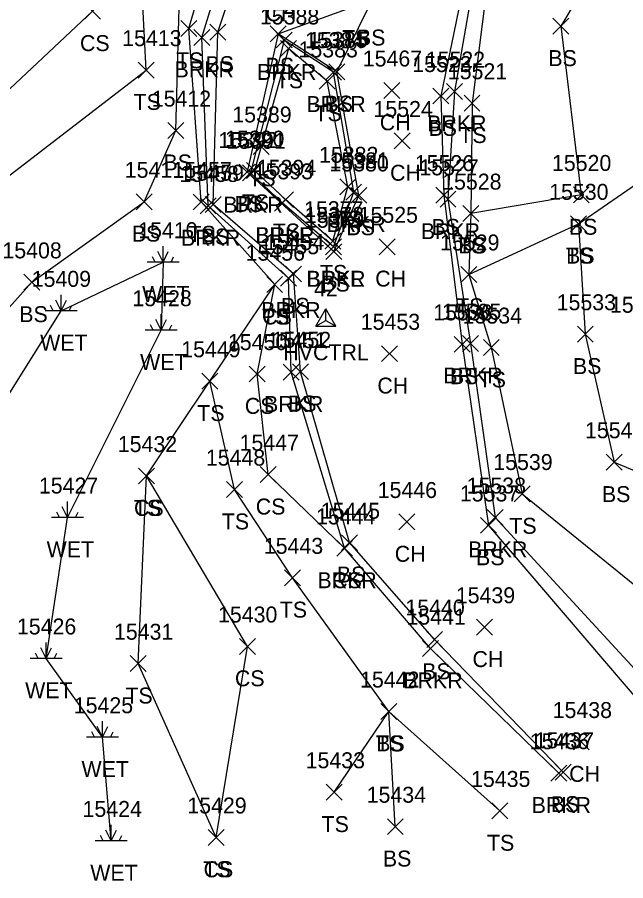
# Model space of a CAD drawing. Extents: x 1606530 to 1613020, y 784959 to 789666.
# Drawn here: x 1609105.8 to 1609182, y 788227.2 to 788335.5 of the extents above; entities that cross this region are included whole.
import ezdxf

# ---------------------------------------------------------------- set-up
doc = ezdxf.new("R2010")
doc.units = 0
for name, color, linetype in [('C_A', 7, 'Continuous'), ('C_I', 7, 'Continuous'), ('CPSM', 7, 'Continuous'), ('L_A', 7, 'Continuous'), ('L_I', 7, 'Continuous'), ('L_TIC', 7, 'Continuous'), ('LAWE', 7, 'Continuous'), ('LELB', 7, 'Continuous'), ('LWET', 7, 'Continuous')]:
    doc.layers.add(name, color=color, linetype=linetype)

msp = doc.modelspace()

# ---------------------------------------------------------------- linework, layer by layer
at = {"layer": 'CPSM'}
for p, q in [((1609143.18, 788296.73), (1609144.43, 788298.9)), ((1609145.68, 788296.73), (1609144.43, 788298.9)), ((1609144.43, 788297.45), (1609144.43, 788298.9)), ((1609143.18, 788296.73), (1609144.43, 788297.45)), ((1609144.43, 788297.45), (1609144.43, 788297.45)), ((1609144.43, 788297.45), (1609145.68, 788296.73)), ((1609143.18, 788296.73), (1609145.68, 788296.73))]:
    msp.add_line(p, q, dxfattribs=at)
at = {"layer": 'L_TIC'}
for points in [[(1609114.19, 788335.22), (1609116.19, 788337.22)], [(1609116.19, 788335.22), (1609114.19, 788337.22)], [(1609126.26, 788333.06), (1609128.26, 788335.06)], [(1609128.26, 788333.06), (1609126.26, 788335.06)], [(1609172.89, 788333.34), (1609174.89, 788335.34)], [(1609174.89, 788333.34), (1609172.89, 788335.34)], [(1609127.89, 788331.92), (1609129.89, 788333.92)], [(1609129.89, 788331.92), (1609127.89, 788333.92)], [(1609129.92, 788332.58), (1609131.92, 788334.58)], [(1609131.92, 788332.58), (1609129.92, 788334.58)], [(1609137.46, 788332.38), (1609139.46, 788334.38)], [(1609139.46, 788332.38), (1609137.46, 788334.38)], [(1609138.23, 788331.61), (1609140.23, 788333.61)], [(1609140.23, 788331.61), (1609138.23, 788333.61)], [(1609138.77, 788330.56), (1609140.77, 788332.56)], [(1609140.77, 788330.56), (1609138.77, 788332.56)], [(1609120.94, 788327.84), (1609122.94, 788329.84)], [(1609122.94, 788327.84), (1609120.94, 788329.84)], [(1609144.41, 788327.58), (1609146.41, 788329.58)], [(1609146.41, 788327.58), (1609144.41, 788329.58)], [(1609144.83, 788327.63), (1609146.83, 788329.63)], [(1609146.83, 788327.63), (1609144.83, 788329.63)], [(1609143.61, 788326.43), (1609145.61, 788328.43)], [(1609145.61, 788326.43), (1609143.61, 788328.43)], [(1609151.71, 788325.29), (1609153.71, 788327.29)], [(1609153.71, 788325.29), (1609151.71, 788327.29)], [(1609157.86, 788324.59), (1609159.86, 788326.59)], [(1609159.86, 788324.59), (1609157.86, 788326.59)], [(1609159.55, 788325.15), (1609161.55, 788327.15)], [(1609161.55, 788325.15), (1609159.55, 788327.15)], [(1609161.76, 788323.69), (1609163.76, 788325.69)], [(1609163.76, 788323.69), (1609161.76, 788325.69)], [(1609124.65, 788320.26), (1609126.65, 788322.26)], [(1609126.65, 788320.26), (1609124.65, 788322.26)], [(1609153, 788318.96), (1609155, 788320.96)], [(1609155, 788318.96), (1609153, 788320.96)], [(1609135.32, 788318.27), (1609137.32, 788320.27)], [(1609137.32, 788318.27), (1609135.32, 788320.27)], [(1609133.57, 788315.06), (1609135.57, 788317.06)], [(1609135.57, 788315.06), (1609133.57, 788317.06)], [(1609133.57, 788315.06), (1609135.57, 788317.06)], [(1609135.57, 788315.06), (1609133.57, 788317.06)], [(1609134.01, 788314.97), (1609136.01, 788316.97)], [(1609136.01, 788314.97), (1609134.01, 788316.97)], [(1609134.49, 788315.24), (1609136.49, 788317.24)], [(1609136.49, 788315.24), (1609134.49, 788317.24)], [(1609146.18, 788313.21), (1609148.18, 788315.21)], [(1609148.18, 788313.21), (1609146.18, 788315.21)], [(1609146.93, 788312.52), (1609148.93, 788314.52)], [(1609148.93, 788312.52), (1609146.93, 788314.52)], [(1609138.38, 788311.59), (1609140.38, 788313.59)], [(1609140.38, 788311.59), (1609138.38, 788313.59)], [(1609138.38, 788311.59), (1609140.38, 788313.59)], [(1609140.38, 788311.59), (1609138.38, 788313.59)], [(1609147.57, 788312.13), (1609149.57, 788314.13)], [(1609149.57, 788312.13), (1609147.57, 788314.13)], [(1609158.24, 788312.17), (1609160.24, 788314.17)], [(1609160.24, 788312.17), (1609158.24, 788314.17)], [(1609158.75, 788311.64), (1609160.75, 788313.64)], [(1609160.75, 788311.64), (1609158.75, 788313.64)], [(1609175.46, 788312.19), (1609177.46, 788314.19)], [(1609177.46, 788312.19), (1609175.46, 788314.19)], [(1609120.69, 788311.33), (1609122.69, 788313.33)], [(1609122.69, 788311.33), (1609120.69, 788313.33)], [(1609127.81, 788311.3), (1609129.81, 788313.3)], [(1609129.81, 788311.3), (1609127.81, 788313.3)], [(1609128.69, 788310.81), (1609130.69, 788312.81)], [(1609130.69, 788310.81), (1609128.69, 788312.81)], [(1609129.33, 788310.97), (1609131.33, 788312.97)], [(1609131.33, 788310.97), (1609129.33, 788312.97)], [(1609137.99, 788311.14), (1609139.99, 788313.14)], [(1609139.99, 788311.14), (1609137.99, 788313.14)], [(1609137.99, 788311.14), (1609139.99, 788313.14)], [(1609139.99, 788311.14), (1609137.99, 788313.14)], [(1609161.61, 788309.85), (1609163.61, 788311.85)], [(1609163.61, 788309.85), (1609161.61, 788311.85)], [(1609161.61, 788309.85), (1609163.61, 788311.85)], [(1609163.61, 788309.85), (1609161.61, 788311.85)], [(1609175.11, 788308.57), (1609177.11, 788310.57)], [(1609177.11, 788308.57), (1609175.11, 788310.57)], [(1609175.11, 788308.57), (1609177.11, 788310.57)], [(1609177.11, 788308.57), (1609175.11, 788310.57)], [(1609144.3, 788306.4), (1609146.3, 788308.4)], [(1609146.3, 788306.4), (1609144.3, 788308.4)], [(1609144.3, 788306.4), (1609146.3, 788308.4)], [(1609146.3, 788306.4), (1609144.3, 788308.4)], [(1609144.39, 788305.67), (1609146.39, 788307.67)], [(1609146.39, 788305.67), (1609144.39, 788307.67)], [(1609144.39, 788305.67), (1609146.39, 788307.67)], [(1609146.39, 788305.67), (1609144.39, 788307.67)], [(1609144.43, 788305.07), (1609146.43, 788307.07)], [(1609146.43, 788305.07), (1609144.43, 788307.07)], [(1609144.43, 788305.07), (1609146.43, 788307.07)], [(1609146.43, 788305.07), (1609144.43, 788307.07)], [(1609151.14, 788305.69), (1609153.14, 788307.69)], [(1609153.14, 788305.69), (1609151.14, 788307.69)], [(1609138.76, 788301.75), (1609140.76, 788303.75)], [(1609140.76, 788301.75), (1609138.76, 788303.75)], [(1609139.39, 788302.27), (1609141.39, 788304.27)], [(1609141.39, 788302.27), (1609139.39, 788304.27)], [(1609161.36, 788302.22), (1609163.36, 788304.22)], [(1609163.36, 788302.22), (1609161.36, 788304.22)], [(1609161.36, 788302.22), (1609163.36, 788304.22)], [(1609163.36, 788302.22), (1609161.36, 788304.22)], [(1609106.58, 788301.23), (1609108.58, 788303.23)], [(1609108.58, 788301.23), (1609106.58, 788303.23)], [(1609137.03, 788300.94), (1609139.03, 788302.94)], [(1609139.03, 788300.94), (1609137.03, 788302.94)], [(1609137.03, 788300.94), (1609139.03, 788302.94)], [(1609139.03, 788300.94), (1609137.03, 788302.94)], [(1609175.96, 788294.72), (1609177.96, 788296.72)], [(1609177.96, 788294.72), (1609175.96, 788296.72)], [(1609160.54, 788293.45), (1609162.54, 788295.45)], [(1609162.54, 788293.45), (1609160.54, 788295.45)], [(1609161.58, 788293.54), (1609163.58, 788295.54)], [(1609163.58, 788293.54), (1609161.58, 788295.54)], [(1609164.18, 788293.05), (1609166.18, 788295.05)], [(1609166.18, 788293.05), (1609164.18, 788295.05)], [(1609151.41, 788292.28), (1609153.41, 788294.28)], [(1609153.41, 788292.28), (1609151.41, 788294.28)], [(1609134.84, 788289.73), (1609136.84, 788291.73)], [(1609136.84, 788289.73), (1609134.84, 788291.73)], [(1609139.11, 788289.97), (1609141.11, 788291.97)], [(1609141.11, 788289.97), (1609139.11, 788291.97)], [(1609140.26, 788290.02), (1609142.26, 788292.02)], [(1609142.26, 788290.02), (1609140.26, 788292.02)], [(1609128.92, 788288.83), (1609130.92, 788290.83)], [(1609130.92, 788288.83), (1609128.92, 788290.83)], [(1609128.92, 788288.83), (1609130.92, 788290.83)], [(1609130.92, 788288.83), (1609128.92, 788290.83)], [(1609179.59, 788278.67), (1609181.59, 788280.67)], [(1609181.59, 788278.67), (1609179.59, 788280.67)], [(1609120.96, 788276.94), (1609122.96, 788278.94)], [(1609122.96, 788276.94), (1609120.96, 788278.94)], [(1609120.96, 788276.94), (1609122.96, 788278.94)], [(1609122.96, 788276.94), (1609120.96, 788278.94)], [(1609136.22, 788277.11), (1609138.22, 788279.11)], [(1609138.22, 788277.11), (1609136.22, 788279.11)], [(1609132, 788275.24), (1609134, 788277.24)], [(1609134, 788275.24), (1609132, 788277.24)], [(1609168.03, 788274.69), (1609170.03, 788276.69)], [(1609170.03, 788274.69), (1609168.03, 788276.69)], [(1609164.68, 788271.74), (1609166.68, 788273.74)], [(1609166.68, 788271.74), (1609164.68, 788273.74)], [(1609153.59, 788271.18), (1609155.59, 788273.18)], [(1609155.59, 788271.18), (1609153.59, 788273.18)], [(1609163.83, 788270.75), (1609165.83, 788272.75)], [(1609165.83, 788270.75), (1609163.83, 788272.75)], [(1609146.39, 788268.58), (1609148.39, 788270.58)], [(1609148.39, 788268.58), (1609146.39, 788270.58)], [(1609145.8, 788267.87), (1609147.8, 788269.87)], [(1609147.8, 788267.87), (1609145.8, 788269.87)], [(1609145.8, 788267.87), (1609147.8, 788269.87)], [(1609147.8, 788267.87), (1609145.8, 788269.87)], [(1609139.26, 788264.18), (1609141.26, 788266.18)], [(1609141.26, 788264.18), (1609139.26, 788266.18)], [(1609163.33, 788257.98), (1609165.33, 788259.98)], [(1609165.33, 788257.98), (1609163.33, 788259.98)], [(1609157.08, 788256.45), (1609159.08, 788258.45)], [(1609159.08, 788256.45), (1609157.08, 788258.45)], [(1609133.61, 788255.57), (1609135.61, 788257.57)], [(1609135.61, 788255.57), (1609133.61, 788257.57)], [(1609156.57, 788255.3), (1609158.57, 788257.3)], [(1609158.57, 788255.3), (1609156.57, 788257.3)], [(1609119.92, 788253.41), (1609121.92, 788255.41)], [(1609121.92, 788253.41), (1609119.92, 788255.41)], [(1609151.32, 788247.41), (1609153.32, 788249.41)], [(1609153.32, 788247.41), (1609151.32, 788249.41)], [(1609151.32, 788247.41), (1609153.32, 788249.41)], [(1609153.32, 788247.41), (1609151.32, 788249.41)], [(1609151.32, 788247.41), (1609153.32, 788249.41)], [(1609153.32, 788247.41), (1609151.32, 788249.41)], [(1609175.46, 788243.59), (1609177.46, 788245.59)], [(1609177.46, 788243.59), (1609175.46, 788245.59)], [(1609172.65, 788239.68), (1609174.65, 788241.68)], [(1609174.65, 788239.68), (1609172.65, 788241.68)], [(1609173.2, 788239.79), (1609175.2, 788241.79)], [(1609175.2, 788239.79), (1609173.2, 788241.79)], [(1609144.5, 788237.29), (1609146.5, 788239.29)], [(1609146.5, 788237.29), (1609144.5, 788239.29)], [(1609165.23, 788234.95), (1609167.23, 788236.95)], [(1609167.23, 788234.95), (1609165.23, 788236.95)], [(1609165.23, 788234.95), (1609167.23, 788236.95)], [(1609167.23, 788234.95), (1609165.23, 788236.95)], [(1609152.15, 788232.97), (1609154.15, 788234.97)], [(1609154.15, 788232.97), (1609152.15, 788234.97)], [(1609129.68, 788231.62), (1609131.68, 788233.62)], [(1609131.68, 788231.62), (1609129.68, 788233.62)], [(1609129.68, 788231.62), (1609131.68, 788233.62)], [(1609131.68, 788231.62), (1609129.68, 788233.62)]]:
    msp.add_lwpolyline(points, dxfattribs=at)
at = {"layer": 'LAWE'}
for points in [[(1609173.65, 788240.68), (1609157.57, 788256.3), (1609146.8, 788268.87), (1609140.11, 788290.97), (1609139.76, 788302.75), (1609129.69, 788311.81), (1609128.89, 788332.92), (1609134.82, 788352.28), (1609140.94, 788359.53), (1609147.89, 788364.33), (1609159.94, 788373.54), (1609169.27, 788374.83), (1609179.54, 788381.79), (1609181.94, 788380.54), (1609177.68, 788370.1), (1609176.3, 788365.9)], [(1609171.99, 788355.54), (1609163.51, 788343.02), (1609160.55, 788326.15), (1609159.75, 788312.64), (1609162.58, 788294.54), (1609165.68, 788272.74), (1609187.56, 788248.97)], [(1609145.39, 788306.67), (1609147.93, 788313.52), (1609145.41, 788328.58), (1609139.23, 788332.61), (1609135.01, 788315.97), (1609138.99, 788312.14)], [(1609145.39, 788306.67), (1609138.99, 788312.14)]]:
    msp.add_lwpolyline(points, dxfattribs=at)
at = {"layer": 'LELB'}
for points in [[(1609065.63, 788267.33), (1609081.96, 788290.89), (1609101.74, 788313.34), (1609121.94, 788328.84), (1609120.75, 788351.64), (1609128.03, 788374.5), (1609144.73, 788378.4), (1609178.08, 788389.18), (1609191.96, 788391.41), (1609197.67, 788378.65), (1609184.8, 788360.05), (1609179.63, 788359.13)], [(1609204.42, 788391.29), (1609206.07, 788363.94), (1609189.17, 788355.52), (1609182.6, 788348.95), (1609173.89, 788334.34), (1609176.46, 788313.19), (1609162.61, 788310.85)], [(1609053.66, 788273.38), (1609077.55, 788293.59), (1609095.85, 788318.07), (1609115.19, 788336.22), (1609111.13, 788353.77), (1609121.97, 788374.07), (1609132.13, 788390.34), (1609178.08, 788389.18)], [(1609081.23, 788263.4), (1609089.39, 788281.95), (1609107.58, 788302.23), (1609121.69, 788312.33), (1609125.65, 788321.26), (1609126.42, 788350.58), (1609137.6, 788366.8), (1609155.35, 788377.55), (1609174.45, 788383.67)], [(1609174.2, 788240.79), (1609158.08, 788257.45), (1609147.39, 788269.58), (1609141.26, 788291.02), (1609140.39, 788303.27), (1609130.33, 788311.97), (1609130.92, 788333.58), (1609136.63, 788350.87), (1609143.46, 788357.67), (1609150.97, 788364.89), (1609158.15, 788371.93), (1609169.44, 788373.41), (1609179.54, 788381.79)], [(1609181.94, 788380.54), (1609177.62, 788370.24), (1609175.84, 788366.16), (1609170.24, 788364.55), (1609169.24, 788358.22), (1609162.45, 788343.09), (1609158.86, 788325.59), (1609159.24, 788313.17), (1609161.54, 788294.45), (1609164.83, 788271.75), (1609186.74, 788246.08)], [(1609166.23, 788235.95), (1609152.32, 788248.41), (1609140.26, 788265.18), (1609133, 788276.24), (1609129.92, 788289.83), (1609138.03, 788301.94), (1609128.81, 788312.3), (1609127.26, 788334.06), (1609133.18, 788354.35)], [(1609164.85, 788341.25), (1609162.76, 788324.69), (1609162.61, 788310.85), (1609162.36, 788303.22), (1609165.18, 788294.05), (1609169.03, 788275.69), (1609193.53, 788255.86)], [(1609138.46, 788333.38), (1609148.06, 788336.85)], [(1609145.83, 788328.63), (1609149.9, 788336.92)], [(1609145.43, 788306.07), (1609148.57, 788313.13), (1609145.83, 788328.63), (1609138.46, 788333.38), (1609134.57, 788316.06)], [(1609145.3, 788307.4), (1609147.18, 788314.21), (1609144.61, 788327.43), (1609139.77, 788331.56), (1609136.32, 788319.27), (1609135.49, 788316.24), (1609139.38, 788312.59)], [(1609145.43, 788306.07), (1609134.57, 788316.06)], [(1609162.36, 788303.22), (1609176.11, 788309.57), (1609185.79, 788316.24)], [(1609145.3, 788307.4), (1609139.38, 788312.59)], [(1609176.11, 788309.57), (1609176.96, 788295.72), (1609180.59, 788279.67), (1609198.21, 788272.31), (1609221.75, 788272.74)], [(1609146.8, 788268.87), (1609137.22, 788278.11), (1609135.84, 788290.73), (1609138.03, 788301.94)], [(1609130.68, 788232.62), (1609120.92, 788254.41), (1609121.96, 788277.94), (1609129.92, 788289.83)], [(1609130.68, 788232.62), (1609134.61, 788256.57), (1609121.96, 788277.94)], [(1609145.5, 788238.29), (1609152.32, 788248.41)], [(1609153.15, 788233.97), (1609152.32, 788248.41)]]:
    msp.add_lwpolyline(points, dxfattribs=at)
at = {"layer": 'LWET'}
for p, q in [((1609124.04, 788304.76), (1609123.37, 788306.1)), ((1609124.04, 788304.76), (1609124.04, 788306.76)), ((1609124.04, 788304.76), (1609124.7, 788306.1)), ((1609126.04, 788304.76), (1609122.04, 788304.76)), ((1609123.04, 788304.76), (1609122.7, 788305.43)), ((1609125.04, 788304.76), (1609125.37, 788305.43)), ((1609111.26, 788298.66), (1609111.26, 788300.66)), ((1609110.26, 788298.66), (1609109.93, 788299.32)), ((1609111.26, 788298.66), (1609110.59, 788299.99)), ((1609111.26, 788298.66), (1609111.93, 788299.99)), ((1609112.26, 788298.66), (1609112.59, 788299.32)), ((1609113.26, 788298.66), (1609109.26, 788298.66)), ((1609123.79, 788296.23), (1609123.79, 788298.23)), ((1609123.79, 788296.23), (1609123.79, 788298.23)), ((1609123.79, 788296.23), (1609123.12, 788297.57)), ((1609123.79, 788296.23), (1609123.12, 788297.57)), ((1609123.79, 788296.23), (1609124.46, 788297.57)), ((1609123.79, 788296.23), (1609124.46, 788297.57)), ((1609125.79, 788296.23), (1609121.79, 788296.23)), ((1609125.79, 788296.23), (1609121.79, 788296.23)), ((1609122.79, 788296.23), (1609122.46, 788296.9)), ((1609122.79, 788296.23), (1609122.46, 788296.9)), ((1609124.79, 788296.23), (1609125.12, 788296.9)), ((1609124.79, 788296.23), (1609125.12, 788296.9)), ((1609112.07, 788272.74), (1609112.07, 788274.74)), ((1609111.07, 788272.74), (1609110.74, 788273.41)), ((1609112.07, 788272.74), (1609111.41, 788274.08)), ((1609112.07, 788272.74), (1609112.74, 788274.08)), ((1609113.07, 788272.74), (1609113.41, 788273.41)), ((1609114.07, 788272.74), (1609110.07, 788272.74)), ((1609109.38, 788255.07), (1609109.38, 788257.07)), ((1609109.38, 788255.07), (1609108.71, 788256.4)), ((1609109.38, 788255.07), (1609110.04, 788256.4)), ((1609111.38, 788255.07), (1609107.38, 788255.07)), ((1609108.38, 788255.07), (1609108.04, 788255.73)), ((1609110.38, 788255.07), (1609110.71, 788255.73)), ((1609116.44, 788245.19), (1609115.78, 788246.52)), ((1609116.44, 788245.19), (1609116.44, 788247.19)), ((1609116.44, 788245.19), (1609117.11, 788246.52)), ((1609118.44, 788245.19), (1609114.44, 788245.19)), ((1609115.44, 788245.19), (1609115.11, 788245.85)), ((1609117.44, 788245.19), (1609117.78, 788245.85)), ((1609117.54, 788232.19), (1609116.87, 788233.52)), ((1609117.54, 788232.19), (1609117.54, 788234.19)), ((1609117.54, 788232.19), (1609118.2, 788233.52)), ((1609119.54, 788232.19), (1609115.54, 788232.19)), ((1609116.54, 788232.19), (1609116.2, 788232.85)), ((1609118.54, 788232.19), (1609118.87, 788232.85))]:
    msp.add_line(p, q, dxfattribs=at)
for points in [[(1609085.89, 788247.41), (1609101.4, 788259.97), (1609094.11, 788271.28), (1609111.26, 788298.66), (1609124.04, 788304.76), (1609123.79, 788296.23)], [(1609117.54, 788232.19), (1609116.44, 788245.19), (1609109.38, 788255.07), (1609112.07, 788272.74), (1609123.79, 788296.23)]]:
    msp.add_lwpolyline(points, dxfattribs=at)

# ---------------------------------------------------------------- texts
at = {"layer": 'C_A'}
msp.add_text('HVCTRL', height=2, dxfattribs=at).set_placement((1609139.12, 788292.45))
at = {"layer": 'C_I'}
msp.add_text('42', height=2, dxfattribs=at).set_placement((1609142.96, 788300.45))
at = {"layer": 'L_A'}
for s, p in [('CH', (1609136.89, 788334.96)), ('BS', (1609148.34, 788331.92)), ('CS', (1609113.63, 788331.22)), ('TS', (1609146.47, 788331.85)), ('TS', (1609125.67, 788329.06)), ('BS', (1609172.33, 788329.34)), ('BRKR', (1609125.48, 788327.92)), ('BS', (1609129.36, 788328.58)), ('BRKR', (1609135.82, 788327.61)), ('BS', (1609136.9, 788328.38)), ('TS', (1609138.18, 788326.56)), ('TS', (1609120.35, 788323.84)), ('BRKR', (1609142.01, 788323.58)), ('BS', (1609144.27, 788323.63)), ('TS', (1609143.02, 788322.43)), ('CH', (1609151.2, 788321.29)), ('BRKR', (1609157.14, 788321.15)), ('BS', (1609157.3, 788320.59)), ('TS', (1609161.17, 788319.69)), ('BS', (1609124.09, 788316.26)), ('CH', (1609152.49, 788314.96)), ('TS', (1609134.73, 788314.27)), ('BRKR', (1609131.6, 788310.97)), ('BS', (1609133.01, 788311.06)), ('BS', (1609133.01, 788311.06)), ('TS', (1609133.9, 788311.24)), ('TS', (1609145.59, 788309.21)), ('BRKR', (1609144.52, 788308.52)), ('BS', (1609147.01, 788308.13)), ('BS', (1609157.68, 788308.17)), ('BS', (1609174.9, 788308.19)), ('BS', (1609120.13, 788307.33)), ('TS', (1609127.22, 788307.3)), ('BS', (1609128.77, 788306.97)), ('BRKR', (1609135.58, 788307.14)), ('BRKL', (1609135.64, 788307.14)), ('TS', (1609137.79, 788307.59)), ('TS', (1609137.79, 788307.59)), ('BRKR', (1609156.34, 788307.64)), ('BRKR', (1609126.28, 788306.81)), ('TS', (1609161.02, 788305.85)), ('BS', (1609161.05, 788305.85)), ('TS', (1609174.52, 788304.57)), ('BS', (1609174.55, 788304.57)), ('BRKR', (1609141.98, 788301.67)), ('BRKL', (1609142.04, 788301.67)), ('TS', (1609143.71, 788302.4)), ('TS', (1609143.71, 788302.4)), ('CH', (1609150.63, 788301.69)), ('BS', (1609143.87, 788301.07)), ('BS', (1609143.87, 788301.07)), ('WET', (1609121.42, 788299.76)), ('BS', (1609106.02, 788297.23)), ('BRKR', (1609136.35, 788297.75)), ('BS', (1609138.83, 788298.27)), ('TS', (1609160.77, 788298.22)), ('TS', (1609160.77, 788298.22)), ('TS', (1609136.44, 788296.94)), ('CS', (1609136.47, 788296.94)), ('WET', (1609108.64, 788293.66)), ('WET', (1609121.17, 788291.23)), ('WET', (1609121.17, 788291.23)), ('BS', (1609175.41, 788290.72)), ('BRKR', (1609159.17, 788289.54)), ('BS', (1609159.99, 788289.45)), ('TS', (1609163.59, 788289.05)), ('CH', (1609150.9, 788288.28)), ('CS', (1609134.29, 788285.73)), ('BRKR', (1609136.7, 788285.97)), ('BS', (1609139.7, 788286.02)), ('TS', (1609128.33, 788284.83)), ('TS', (1609128.33, 788284.83)), ('BS', (1609179.04, 788274.67)), ('TS', (1609120.37, 788272.94)), ('CS', (1609120.4, 788272.94)), ('CS', (1609135.66, 788273.11)), ('TS', (1609131.41, 788271.24)), ('TS', (1609167.44, 788270.69)), ('WET', (1609109.45, 788267.74)), ('CH', (1609153.08, 788267.18)), ('BRKR', (1609162.27, 788267.74)), ('BS', (1609163.27, 788266.75)), ('BRKR', (1609143.39, 788263.87)), ('CS', (1609145.24, 788263.87)), ('BS', (1609145.83, 788264.58)), ('TS', (1609138.67, 788260.18)), ('CH', (1609162.82, 788253.98)), ('BS', (1609156.52, 788252.45)), ('CS', (1609133.05, 788251.57)), ('BRKR', (1609154.16, 788251.3)), ('WET', (1609106.76, 788250.07)), ('TS', (1609119.32, 788249.41)), ('TS', (1609150.73, 788243.41)), ('TS', (1609150.73, 788243.41)), ('BS', (1609150.76, 788243.41)), ('WET', (1609113.82, 788240.19)), ('CH', (1609174.94, 788239.59)), ('BRKR', (1609170.24, 788235.68)), ('BS', (1609172.64, 788235.79)), ('TS', (1609143.91, 788233.29)), ('TS', (1609164.64, 788230.95)), ('TS', (1609164.64, 788230.95)), ('BS', (1609151.59, 788228.97)), ('WET', (1609114.92, 788227.19)), ('TS', (1609129.09, 788227.62)), ('CS', (1609129.12, 788227.62))]:
    msp.add_text(s, height=2, dxfattribs=at).set_placement(p)
at = {"layer": 'L_I'}
for s, p in [('15388', (1609136.18, 788334.56)), ('15413', (1609118.92, 788331.84)), ('15384', (1609141.82, 788331.58)), ('15385', (1609142.24, 788331.63)), ('15383', (1609141.02, 788330.43)), ('15467', (1609149.07, 788329.29)), ('15522', (1609156.96, 788329.15)), ('15523', (1609155.27, 788328.59)), ('15521', (1609159.73, 788327.69)), ('15412', (1609122.63, 788324.26)), ('15389', (1609132.72, 788322.27)), ('15524', (1609150.41, 788322.96)), ('15392', (1609130.98, 788319.06)), ('15392', (1609130.98, 788319.06)), ('15390', (1609131.81, 788319.24)), ('15391', (1609131.99, 788318.97)), ('15382', (1609143.59, 788317.21)), ('15380', (1609144.89, 788316.13)), ('15381', (1609144.91, 788316.52)), ('15526', (1609155.59, 788316.17)), ('15527', (1609156.16, 788315.64)), ('15520', (1609172.78, 788316.19)), ('15411', (1609119.24, 788315.33)), ('15457', (1609125.22, 788315.3)), ('15458', (1609126.1, 788314.81)), ('15459', (1609126.73, 788314.97)), ('15393', (1609135.4, 788315.14)), ('15393', (1609135.4, 788315.14)), ('15394', (1609135.79, 788315.59)), ('15394', (1609135.79, 788315.59)), ('15528', (1609159.02, 788313.85)), ('15528', (1609159.02, 788313.85)), ('15530', (1609172.43, 788312.57)), ('15530', (1609172.43, 788312.57)), ('15377', (1609141.71, 788310.4)), ('15377', (1609141.71, 788310.4)), ('15378', (1609141.8, 788309.67)), ('15378', (1609141.8, 788309.67)), ('15525', (1609148.55, 788309.69)), ('15379', (1609141.83, 788309.07)), ('15379', (1609141.83, 788309.07)), ('15410', (1609120.93, 788307.76)), ('15454', (1609136.8, 788306.27)), ('15529', (1609158.76, 788306.22)), ('15529', (1609158.76, 788306.22)), ('15408', (1609103.91, 788305.23)), ('15456', (1609134.39, 788304.94)), ('15456', (1609134.39, 788304.94)), ('15455', (1609136.17, 788305.75)), ('15409', (1609107.58, 788301.66)), ('15428', (1609120.2, 788299.23)), ('15428', (1609120.2, 788299.23)), ('15533', (1609173.37, 788298.72)), ('15532', (1609180.05, 788298.41)), ('15536', (1609157.9, 788297.45)), ('15535', (1609158.99, 788297.54)), ('15453', (1609148.82, 788296.28)), ('15534', (1609161.59, 788297.05)), ('15452', (1609137.67, 788294.02)), ('15450', (1609132.17, 788293.73)), ('15451', (1609137.09, 788293.97)), ('15449', (1609126.32, 788292.83)), ('15449', (1609126.32, 788292.83)), ('15540', (1609176.92, 788282.67)), ('15447', (1609133.63, 788281.11)), ('15432', (1609118.37, 788280.94)), ('15432', (1609118.37, 788280.94)), ('15448', (1609129.41, 788279.24)), ('15539', (1609165.43, 788278.69)), ('15427', (1609108.48, 788275.74)), ('15538', (1609162.09, 788275.74)), ('15446', (1609150.94, 788275.18)), ('15537', (1609161.24, 788274.75)), ('15445', (1609143.8, 788272.58)), ('15444', (1609143.21, 788271.87)), ('15444', (1609143.21, 788271.87)), ('15443', (1609136.67, 788268.18)), ('15439', (1609160.73, 788261.98)), ('15440', (1609154.41, 788260.45)), ('15430', (1609130.93, 788259.57)), ('15441', (1609154.54, 788259.3)), ('15426', (1609105.73, 788258.07)), ('15431', (1609117.89, 788257.41)), ('15442', (1609148.73, 788251.41)), ('15442', (1609148.73, 788251.41)), ('15442', (1609148.73, 788251.41)), ('15425', (1609112.85, 788248.19)), ('15438', (1609172.87, 788247.59)), ('15436', (1609170, 788243.68)), ('15437', (1609170.61, 788243.79)), ('15433', (1609141.91, 788241.29)), ('15435', (1609162.64, 788238.95)), ('15435', (1609162.64, 788238.95)), ('15434', (1609149.56, 788236.97)), ('15429', (1609127.08, 788235.62)), ('15429', (1609127.08, 788235.62)), ('15424', (1609113.95, 788235.19))]:
    msp.add_text(s, height=2, dxfattribs=at).set_placement(p)

doc.saveas('drawing.dxf')
